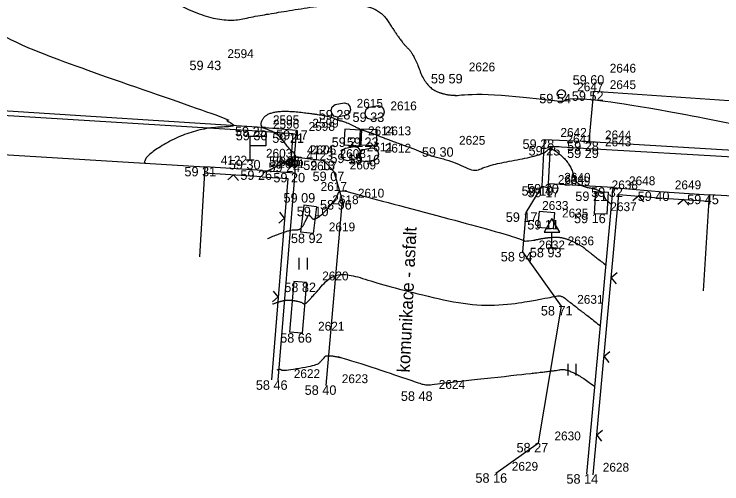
# Model space of a CAD drawing. Extents: x -704017 to -701500, y -1008977 to -1008450.
# Drawn here: x -702593.72 to -702571.32, y -1008776.87 to -1008762.02 of the extents above; entities that cross this region are included whole.
import ezdxf

# ---------------------------------------------------------------- set-up
doc = ezdxf.new("R2010")
doc.units = 0
for name, color, linetype in [('Z_body', 7, 'Continuous'), ('Z_body_cisla', 7, 'Continuous'), ('Z_body_vysky', 7, 'Continuous'), ('Z_budovy', 7, 'Continuous'), ('Z_chodnik', 7, 'Continuous'), ('Z_dopravni_znaceni', 7, 'Continuous'), ('Z_komunikace', 7, 'Continuous'), ('Z_obruby', 7, 'Continuous'), ('Z_oploceni', 7, 'Continuous'), ('Z_popis', 7, 'Continuous'), ('Z_rozhrani_ploch', 7, 'Continuous'), ('Z_site_znaky_nerozlisene', 7, 'Continuous'), ('Z_site_znaky_pilire', 7, 'Continuous'), ('Z_site_znaky_plynovod', 7, 'Continuous'), ('Z_site_znaky_vodovod', 7, 'Continuous'), ('Z_sloupy', 7, 'Continuous'), ('Z_vrstevnice_hlavni', 7, 'Continuous'), ('Z_vrstevnice_vedlejsi', 7, 'Continuous')]:
    doc.layers.add(name, color=color, linetype=linetype)

# ---------------------------------------------------------------- blocks, each defined once
blk = doc.blocks.new('POINT_DISPLAY')
blk.add_line((0, 0), (0, 0))
blk = doc.blocks.new('Z212')
for p, q in [((-0.17, 0.17), (0, 0)), ((0, 0), (0.17, 0.17))]:
    blk.add_line(p, q)
blk = doc.blocks.new('Z306')
for p, q in [((-0.13, 0.17), (-0.13, -0.2)), ((0.13, 0.17), (0.13, -0.2))]:
    blk.add_line(p, q)
blk = doc.blocks.new('Z527')
for p, q in [((0, 0.93), (-0.25, 0.5)), ((0.25, 0.5), (0, 0.93)), ((-0.25, 0.5), (0.25, 0.5)), ((0, 0), (0, 0.5)), ((-0.13, 0), (0.13, 0))]:
    blk.add_line(p, q)
blk = doc.blocks.new('Z524')
for p, q in [((0, 0), (0, 0.75)), ((0, 0.75), (0.5, 0.75)), ((0.5, 0.75), (0.5, 0.45)), ((0.5, 0.45), (0, 0.45)), ((-0.13, 0), (0.13, 0))]:
    blk.add_line(p, q)
blk = doc.blocks.new('Z601')
for p, q in [((-0.13, 0.03), (-0.1, 0.08)), ((-0.13, -0.03), (-0.13, 0.03)), ((-0.1, 0.08), (-0.08, 0.1)), ((-0.08, 0.1), (-0.03, 0.13)), ((-0.08, 0.05), (-0.08, -0.05)), ((-0.03, 0.13), (0.03, 0.13)), ((-0.03, -0.08), (-0.03, 0.08)), ((-0.03, 0.08), (0.03, 0.08)), ((0.03, 0.13), (0.08, 0.1)), ((0.03, 0.08), (0.03, -0.08)), ((0.08, 0.1), (0.1, 0.08)), ((0.08, -0.05), (0.08, 0.05)), ((0.1, 0.08), (0.13, 0.03)), ((0.13, 0.03), (0.13, -0.03)), ((-0.1, -0.08), (-0.13, -0.03)), ((-0.08, -0.1), (-0.1, -0.08)), ((-0.08, -0.05), (-0.03, -0.08)), ((-0.03, -0.13), (-0.08, -0.1)), ((0.03, -0.13), (-0.03, -0.13)), ((0.03, -0.08), (0.08, -0.05)), ((0.08, -0.1), (0.03, -0.13)), ((0.1, -0.08), (0.08, -0.1)), ((0.13, -0.03), (0.1, -0.08))]:
    blk.add_line(p, q)
blk = doc.blocks.new('Z608')
for p, q in [((0.25, 0.25), (-0.25, 0.25)), ((-0.25, 0.25), (-0.25, -0.25)), ((0.25, -0.25), (0.25, 0.25)), ((-0.25, -0.25), (0.25, -0.25))]:
    blk.add_line(p, q)
blk = doc.blocks.new('Z614')
for p, q in [((-0.13, 0.03), (-0.1, 0.08)), ((-0.13, -0.03), (-0.13, 0.03)), ((-0.1, 0.08), (-0.08, 0.1)), ((-0.08, 0.1), (-0.03, 0.13)), ((-0.03, 0.13), (0.03, 0.13)), ((0.03, 0.13), (0.08, 0.1)), ((0.08, 0.1), (0.1, 0.08)), ((0.1, 0.08), (0.13, 0.03)), ((0.13, 0.03), (0.13, -0.03)), ((-0.1, -0.08), (-0.13, -0.03)), ((-0.08, -0.1), (-0.1, -0.08)), ((-0.03, -0.13), (-0.08, -0.1)), ((0.03, -0.13), (-0.03, -0.13)), ((0.08, -0.1), (0.03, -0.13)), ((0.1, -0.08), (0.08, -0.1)), ((0.13, -0.03), (0.1, -0.08))]:
    blk.add_line(p, q)
blk = doc.blocks.new('Z14')
for p, q in [((-0.3, 0.05), (-0.25, 0.15)), ((-0.3, -0.05), (-0.3, 0.05)), ((-0.25, 0.15), (-0.15, 0.2)), ((-0.15, 0.2), (0.15, 0.2)), ((0.15, 0.2), (0.25, 0.15)), ((0.25, 0.15), (0.3, 0.05)), ((0.3, 0.05), (0.3, -0.05)), ((-0.25, -0.15), (-0.3, -0.05)), ((-0.15, -0.2), (-0.25, -0.15)), ((0.15, -0.2), (-0.15, -0.2)), ((0.25, -0.15), (0.15, -0.2)), ((0.3, -0.05), (0.25, -0.15))]:
    blk.add_line(p, q)

msp = doc.modelspace()

# ---------------------------------------------------------------- linework, layer by layer
at = {"layer": 'Z_budovy'}
for p, q in [((-702600.66, -1008766.06), (-702587.68, -1008766.85)), ((-702587.68, -1008766.85), (-702587.85, -1008769.69)), ((-702571.72, -1008767.73), (-702571.91, -1008770.77)), ((-702562.71, -1008768.3), (-702571.72, -1008767.73))]:
    msp.add_line(p, q, dxfattribs=at)
at = {"layer": 'Z_chodnik'}
for p, q in [((-702576.81, -1008767.39), (-702576.74, -1008766.19)), ((-702576.74, -1008766.19), (-702575.52, -1008766.27)), ((-702575.52, -1008766.27), (-702563.2, -1008766.99)), ((-702576.82, -1008767.51), (-702576.81, -1008767.39)), ((-702574.76, -1008767.5), (-702576.81, -1008767.39)), ((-702577.01, -1008767.46), (-702576.82, -1008767.51))]:
    msp.add_line(p, q, dxfattribs=at)
at = {"layer": 'Z_komunikace'}
for p, q in [((-702575.52, -1008766.05), (-702575.37, -1008764.46)), ((-702575.37, -1008764.46), (-702563.17, -1008765.28)), ((-702600, -1008764.69), (-702586.03, -1008765.58)), ((-702586.03, -1008765.58), (-702584.78, -1008765.69)), ((-702584.78, -1008765.69), (-702584.86, -1008766.53)), ((-702577.01, -1008767.46), (-702576.93, -1008765.98)), ((-702576.93, -1008765.98), (-702575.52, -1008766.05)), ((-702584.86, -1008766.53), (-702583.92, -1008766.65)), ((-702583.92, -1008766.65), (-702583.6, -1008767)), ((-702583.6, -1008767), (-702583.34, -1008767.9)), ((-702577.51, -1008768.29), (-702577.01, -1008767.46)), ((-702583.34, -1008767.9), (-702583.85, -1008773.76)), ((-702577.62, -1008769.54), (-702577.51, -1008768.29)), ((-702576.4, -1008771.25), (-702577.62, -1008769.54)), ((-702577.12, -1008775.58), (-702576.4, -1008771.25)), ((-702578.47, -1008776.54), (-702577.12, -1008775.58))]:
    msp.add_line(p, q, dxfattribs=at)
at = {"layer": 'Z_obruby'}
for p, q in [((-702599.99, -1008764.85), (-702586.03, -1008765.71)), ((-702586.03, -1008765.71), (-702584.9, -1008765.79)), ((-702584.9, -1008765.79), (-702584.95, -1008766.52)), ((-702584.95, -1008766.52), (-702584.86, -1008766.53))]:
    msp.add_line(p, q, dxfattribs=at)
at = {"layer": 'Z_oploceni'}
for p, q in [((-702585.86, -1008766.96), (-702587.68, -1008766.85)), ((-702585.86, -1008766.96), (-702584.84, -1008767.04)), ((-702585.87, -1008767.16), (-702587.69, -1008767.05)), ((-702585.87, -1008767.16), (-702585.06, -1008767.22)), ((-702584.84, -1008767.04), (-702585.37, -1008773.6)), ((-702585.06, -1008767.22), (-702585.57, -1008773.58)), ((-702575.59, -1008776.57), (-702574.76, -1008767.5)), ((-702574.76, -1008767.5), (-702573.31, -1008767.63)), ((-702573.31, -1008767.63), (-702571.72, -1008767.73)), ((-702575.39, -1008776.59), (-702574.58, -1008767.72)), ((-702574.58, -1008767.72), (-702573.33, -1008767.83)), ((-702573.33, -1008767.83), (-702571.73, -1008767.93))]:
    msp.add_line(p, q, dxfattribs=at)
at = {"layer": 'Z_rozhrani_ploch'}
for p, q in [((-702575.52, -1008766.05), (-702563.25, -1008766.78)), ((-702584.86, -1008766.53), (-702584.84, -1008767.04))]:
    msp.add_line(p, q, dxfattribs=at)
at = {"layer": 'Z_site_znaky_pilire'}
for p, q in [((-702575.35, -1008768.33), (-702575.31, -1008767.63)), ((-702575.31, -1008767.63), (-702574.91, -1008767.65)), ((-702574.95, -1008768.35), (-702574.91, -1008767.65)), ((-702584.55, -1008768.06), (-702584.66, -1008768.91)), ((-702584.15, -1008768.11), (-702584.55, -1008768.06)), ((-702584.15, -1008768.11), (-702584.26, -1008768.96)), ((-702574.95, -1008768.35), (-702575.35, -1008768.33)), ((-702584.26, -1008768.96), (-702584.66, -1008768.91)), ((-702584.87, -1008770.48), (-702585, -1008772.08)), ((-702584.47, -1008770.51), (-702584.87, -1008770.48)), ((-702584.47, -1008770.51), (-702584.6, -1008772.11)), ((-702584.6, -1008772.11), (-702585, -1008772.08))]:
    msp.add_line(p, q, dxfattribs=at)
at = {"layer": 'Z_vrstevnice_hlavni'}
msp.add_open_spline([(-702585.701, -1008769.118), (-702584.983, -1008768.813), (-702584.645, -1008768.866), (-702584.426, -1008768.411), (-702584.382, -1008768.358), (-702584.211, -1008768.582), (-702583.571, -1008767.96), (-702583.435, -1008767.573), (-702583.17, -1008767.614), (-702582.964, -1008767.704), (-702578.04, -1008768.988), (-702577.591, -1008769.214), (-702577.359, -1008769.184), (-702576.77, -1008769.068), (-702576.289, -1008769.081), (-702575.723, -1008769.368), (-702575.62, -1008769.467), (-702574.985, -1008769.96)], degree=2, dxfattribs=at)
at = {"layer": 'Z_vrstevnice_vedlejsi'}
for points in [[(-702591.383, -1008747.825), (-702590.503, -1008748.32), (-702589.635, -1008749.437), (-702589.352, -1008749.8), (-702588.838, -1008750.353), (-702587.312, -1008752.004), (-702586.328, -1008752.958), (-702585.68, -1008753.598), (-702585.12, -1008754.1), (-702584.887, -1008754.197), (-702584.278, -1008754.119), (-702583.643, -1008754.408), (-702582.575, -1008755.09), (-702581.96, -1008755.323), (-702582.298, -1008756.122), (-702581.19, -1008757.49), (-702579.27, -1008760.5), (-702576.041, -1008758.779), (-702569.201, -1008761.361), (-702568.264, -1008762.828), (-702562.973, -1008764.163), (-702556.89, -1008763.701), (-702549.17, -1008761.99), (-702548.2, -1008763.05), (-702545.621, -1008759.916), (-702540.471, -1008758.95), (-702540.495, -1008758.093), (-702535.274, -1008757.786), (-702534.25, -1008757.802), (-702533.983, -1008757.74), (-702533.952, -1008757.707), (-702533.743, -1008757.7)], [(-702608.35, -1008750.923), (-702607.79, -1008750.975), (-702606.949, -1008751.042), (-702606.805, -1008751.216), (-702605.86, -1008752.857), (-702605.496, -1008752.826), (-702605.08, -1008752.838), (-702604.448, -1008752.878), (-702603.894, -1008752.928), (-702603.615, -1008752.962), (-702603.346, -1008755.058), (-702603.088, -1008756.226), (-702602.967, -1008756.819), (-702602.544, -1008756.817), (-702601.956, -1008757.316), (-702597.607, -1008758.681), (-702595.703, -1008760.783), (-702594.812, -1008762.252), (-702593.044, -1008763.271), (-702586.03, -1008765.58), (-702587.969, -1008765.591), (-702589.676, -1008766.526), (-702589.58, -1008766.734)], [(-702601.129, -1008751.002), (-702601.021, -1008751.529), (-702599.508, -1008752.74), (-702599.389, -1008752.863), (-702598.7, -1008752.965), (-702598.085, -1008752.893), (-702597.944, -1008752.878), (-702597.5, -1008752.595), (-702597.064, -1008752.314), (-702597.012, -1008752.255), (-702596.725, -1008751.85), (-702596.461, -1008752.662), (-702595.03, -1008754.083), (-702592.708, -1008756.644), (-702590.225, -1008760.739), (-702587.415, -1008762.358), (-702585.644, -1008761.993), (-702582.355, -1008761.511), (-702581.456, -1008762.92), (-702581.08, -1008763.256), (-702580.688, -1008764.332), (-702579.926, -1008764.63), (-702578.988, -1008764.511), (-702576.482, -1008764.762), (-702576.265, -1008764.772), (-702575.383, -1008764.593), (-702565.138, -1008766.668), (-702565.213, -1008766.698), (-702565.171, -1008766.875), (-702566.987, -1008767.319), (-702567.625, -1008767.989)], [(-702585.854, -1008767.043), (-702585.69, -1008766.973), (-702585.415, -1008766.835), (-702584.96, -1008766.615), (-702584.915, -1008766.62), (-702584.857, -1008766.615), (-702584.788, -1008766.539), (-702584.851, -1008766.437), (-702584.868, -1008766.382), (-702584.94, -1008766.374), (-702585.402, -1008765.754), (-702586.03, -1008765.58), (-702585.608, -1008765.013), (-702583.762, -1008765.225), (-702583.488, -1008765.37), (-702583.226, -1008765.423), (-702582.783, -1008765.657), (-702582.454, -1008765.762), (-702581.819, -1008766.009), (-702580.979, -1008766.316), (-702580.611, -1008766.476), (-702579.79, -1008766.69), (-702579.128, -1008767.022), (-702578.717, -1008766.789), (-702576.957, -1008766.473), (-702576.74, -1008766.19), (-702576.093, -1008766.768), (-702575.956, -1008767.436), (-702575.11, -1008767.583), (-702575.018, -1008767.863), (-702574.948, -1008767.93), (-702574.809, -1008768.038)], [(-702585.548, -1008771.193), (-702585.162, -1008771.029), (-702584.645, -1008771.111), (-702584.527, -1008771.21), (-702584.367, -1008771.052), (-702583.531, -1008770.098), (-702582.22, -1008770.547), (-702578.925, -1008771.362), (-702576.612, -1008770.953), (-702576.455, -1008770.915), (-702576.307, -1008770.99), (-702576.292, -1008771.004), (-702575.161, -1008771.881)], [(-702585.394, -1008773.268), (-702585.341, -1008773.245), (-702585.27, -1008773.257), (-702585.216, -1008773.302), (-702584.138, -1008773.125), (-702583.998, -1008772.986), (-702583.759, -1008772.714), (-702580.887, -1008773.698), (-702580.643, -1008773.758), (-702580.399, -1008773.715), (-702576.744, -1008773.317), (-702576.102, -1008773.21), (-702575.337, -1008773.803)]]:
    msp.add_open_spline(points, degree=2, dxfattribs=at)

# ---------------------------------------------------------------- block references
at = {"layer": 'Z_body'}
for p in [(-702587.47, -1008763.49), (-702579.83, -1008763.91), (-702575.37, -1008763.95), (-702575.37, -1008764.46), (-702576.4, -1008764.54), (-702583.38, -1008765.05), (-702582.31, -1008765.13), (-702586.03, -1008765.58), (-702586.03, -1008765.71), (-702584.9, -1008765.79), (-702584.78, -1008765.69), (-702583.02, -1008765.92), (-702582.49, -1008765.92), (-702576.93, -1008765.98), (-702575.52, -1008766.05), (-702580.14, -1008766.23), (-702576.74, -1008766.19), (-702575.52, -1008766.27), (-702584.95, -1008766.52), (-702584.86, -1008766.53), (-702583.06, -1008766.43), (-702582.49, -1008766.47), (-702586.25, -1008766.63), (-702584.97, -1008766.71), (-702583.92, -1008766.65), (-702587.68, -1008766.85), (-702585.86, -1008766.96), (-702584.84, -1008767.04), (-702583.6, -1008767), (-702576.81, -1008767.39), (-702577.01, -1008767.46), (-702576.82, -1008767.51), (-702575.31, -1008767.63), (-702574.76, -1008767.5), (-702573.31, -1008767.63), (-702584.52, -1008767.68), (-702571.72, -1008767.73), (-702583.34, -1008767.9), (-702584.15, -1008768.11), (-702577.51, -1008768.29), (-702576.88, -1008768.53), (-702575.35, -1008768.33), (-702584.26, -1008768.96), (-702576.7, -1008769.41), (-702577.62, -1008769.54), (-702584.47, -1008770.51), (-702576.4, -1008771.25), (-702584.6, -1008772.11), (-702585.37, -1008773.6), (-702583.85, -1008773.76), (-702580.78, -1008773.95), (-702577.12, -1008775.58), (-702578.47, -1008776.54), (-702575.59, -1008776.57)]:
    msp.add_blockref('POINT_DISPLAY', p, dxfattribs=at)
at = {"layer": 'Z_dopravni_znaceni'}
for name, p in [('Z524', (-702586.25, -1008766.63)), ('Z527', (-702576.7, -1008769.41))]:
    msp.add_blockref(name, p, dxfattribs=at)
at = {"layer": 'Z_oploceni'}
for p, rotation in [((-702586.78, -1008767.1), 176.5), ((-702573.95, -1008767.77), 174.9), ((-702572.53, -1008767.88), 176.4), ((-702585.16, -1008768.47), 85.4), ((-702574.82, -1008770.36), -95.19999999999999), ((-702585.36, -1008770.96), 85.4), ((-702575.05, -1008772.85), -95.19999999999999), ((-702575.28, -1008775.34), -95.19999999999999)]:
    msp.add_blockref('Z212', p, dxfattribs=dict(at, rotation=rotation))
at = {"layer": 'Z_popis'}
for p in [(-702584.58, -1008769.9), (-702576.07, -1008773.25)]:
    msp.add_blockref('Z306', p, dxfattribs=at)
at = {"layer": 'Z_site_znaky_nerozlisene'}
for p, rotation in [((-702583.02, -1008765.92), -3.600000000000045), ((-702582.49, -1008765.92), -2.699999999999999), ((-702576.88, -1008768.53), -5.3999999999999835)]:
    msp.add_blockref('Z608', p, dxfattribs=dict(at, rotation=rotation))
at = {"layer": 'Z_site_znaky_plynovod', "rotation": 10.799999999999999}
for p in [(-702583.38, -1008765.05), (-702582.31, -1008765.13), (-702583.06, -1008766.43), (-702582.49, -1008766.47)]:
    msp.add_blockref('Z14', p, dxfattribs=at)
at = {"layer": 'Z_site_znaky_vodovod', "rotation": 10.799999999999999}
msp.add_blockref('Z614', (-702576.4, -1008764.54), dxfattribs=at)
at = {"layer": 'Z_sloupy'}
msp.add_blockref('Z601', (-702584.97, -1008766.71), dxfattribs=at)

# ---------------------------------------------------------------- texts
at = {"layer": 'Z_body_cisla'}
for s, p in [('2594', (-702586.97, -1008763.41)), ('2626', (-702579.33, -1008763.83)), ('2646', (-702574.87, -1008763.87)), ('2647', (-702575.9, -1008764.46)), ('2645', (-702574.87, -1008764.39)), ('2615', (-702582.88, -1008764.98)), ('2616', (-702581.81, -1008765.06)), ('2595', (-702585.53, -1008765.5)), ('2596', (-702585.53, -1008765.64)), ('2599', (-702584.28, -1008765.61)), ('2598', (-702584.4, -1008765.71)), ('2614', (-702582.52, -1008765.85)), ('2613', (-702581.99, -1008765.85)), ('2642', (-702576.43, -1008765.9)), ('2641', (-702576.24, -1008766.11)), ('2644', (-702575.02, -1008765.98)), ('2611', (-702582.56, -1008766.36)), ('2625', (-702579.64, -1008766.15)), ('2643', (-702575.02, -1008766.2)), ('2603', (-702585.75, -1008766.56)), ('4124', (-702584.45, -1008766.45)), ('2606', (-702584.36, -1008766.45)), ('2608', (-702583.42, -1008766.57)), ('2612', (-702581.99, -1008766.4)), ('4122', (-702587.18, -1008766.78)), ('4123', (-702584.47, -1008766.64)), ('2601', (-702585.36, -1008766.89)), ('2607', (-702584.34, -1008766.96)), ('2609', (-702583.1, -1008766.93)), ('2634', (-702576.51, -1008767.39)), ('2639', (-702576.32, -1008767.44)), ('2640', (-702576.31, -1008767.32)), ('2648', (-702574.26, -1008767.43)), ('2617', (-702584.02, -1008767.61)), ('2638', (-702574.81, -1008767.56)), ('2649', (-702572.81, -1008767.56)), ('2610', (-702582.84, -1008767.82)), ('2618', (-702583.65, -1008768.03)), ('2633', (-702577.01, -1008768.21)), ('2637', (-702574.85, -1008768.25)), ('2635', (-702576.38, -1008768.45)), ('2619', (-702583.76, -1008768.89)), ('2632', (-702577.12, -1008769.46)), ('2636', (-702576.2, -1008769.33)), ('2620', (-702583.97, -1008770.44)), ('2631', (-702575.9, -1008771.18)), ('2621', (-702584.1, -1008772.03)), ('2622', (-702584.87, -1008773.53)), ('2623', (-702583.35, -1008773.69)), ('2624', (-702580.28, -1008773.87)), ('2630', (-702576.62, -1008775.5)), ('2629', (-702577.97, -1008776.46)), ('2628', (-702575.09, -1008776.49))]:
    msp.add_text(s, height=0.28, dxfattribs=at).set_placement(p)
at = {"layer": 'Z_body_vysky'}
for s, p in [('59 43', (-702588.17, -1008763.79)), ('59 59', (-702580.53, -1008764.21)), ('59 60', (-702576.045, -1008764.25)), ('59 52', (-702576.07, -1008764.76)), ('59 54', (-702577.1, -1008764.84)), ('59 28', (-702584.08, -1008765.35)), ('59 33', (-702583.01, -1008765.43)), ('59 25', (-702586.73, -1008765.88)), ('59 30', (-702586.705, -1008766.01)), ('59 21', (-702585.55, -1008766.09)), ('59 17', (-702585.43, -1008765.99)), ('59 21', (-702583.67, -1008766.22)), ('59 23', (-702583.19, -1008766.22)), ('59 28', (-702577.63, -1008766.28)), ('59 28', (-702576.22, -1008766.35)), ('59 30', (-702580.815, -1008766.53)), ('59 25', (-702577.44, -1008766.49)), ('59 29', (-702576.22, -1008766.57)), ('59 26', (-702585.65, -1008766.82)), ('59 26', (-702585.56, -1008766.83)), ('59 15', (-702583.71, -1008766.73)), ('59 16', (-702583.14, -1008766.77)), ('59 30', (-702586.925, -1008766.93)), ('59 24', (-702585.67, -1008767.01)), ('59 13', (-702584.57, -1008766.95)), ('59 31', (-702588.33, -1008767.15)), ('59 26', (-702586.56, -1008767.26)), ('59 20', (-702585.515, -1008767.34)), ('59 07', (-702584.275, -1008767.3)), ('59 20', (-702577.485, -1008767.69)), ('59 19', (-702577.66, -1008767.76)), ('59 17', (-702577.47, -1008767.81)), ('59 21', (-702575.96, -1008767.93)), ('59 32', (-702575.46, -1008767.8)), ('59 40', (-702573.985, -1008767.93)), ('59 09', (-702585.195, -1008767.98)), ('59 45', (-702572.42, -1008768.03)), ('58 96', (-702584.04, -1008768.2)), ('59 10', (-702584.775, -1008768.41)), ('59 17', (-702578.16, -1008768.59)), ('59 11', (-702577.48, -1008768.83)), ('59 16', (-702576, -1008768.63)), ('58 92', (-702584.96, -1008769.26)), ('58 93', (-702577.4, -1008769.71)), ('58 94', (-702578.32, -1008769.84)), ('58 82', (-702585.17, -1008770.81)), ('58 71', (-702577.05, -1008771.55)), ('58 66', (-702585.3, -1008772.41)), ('58 46', (-702586.07, -1008773.9)), ('58 40', (-702584.525, -1008774.06)), ('58 48', (-702581.48, -1008774.25)), ('58 27', (-702577.82, -1008775.88)), ('58 16', (-702579.12, -1008776.84)), ('58 14', (-702576.24, -1008776.87))]:
    msp.add_text(s, height=0.3, dxfattribs=at).set_placement(p)
at = {"layer": 'Z_popis'}
msp.add_text('komunikace - asfalt', height=0.4, rotation=87.3, dxfattribs=at).set_placement((-702581.2, -1008773.36))

doc.saveas('drawing.dxf')
